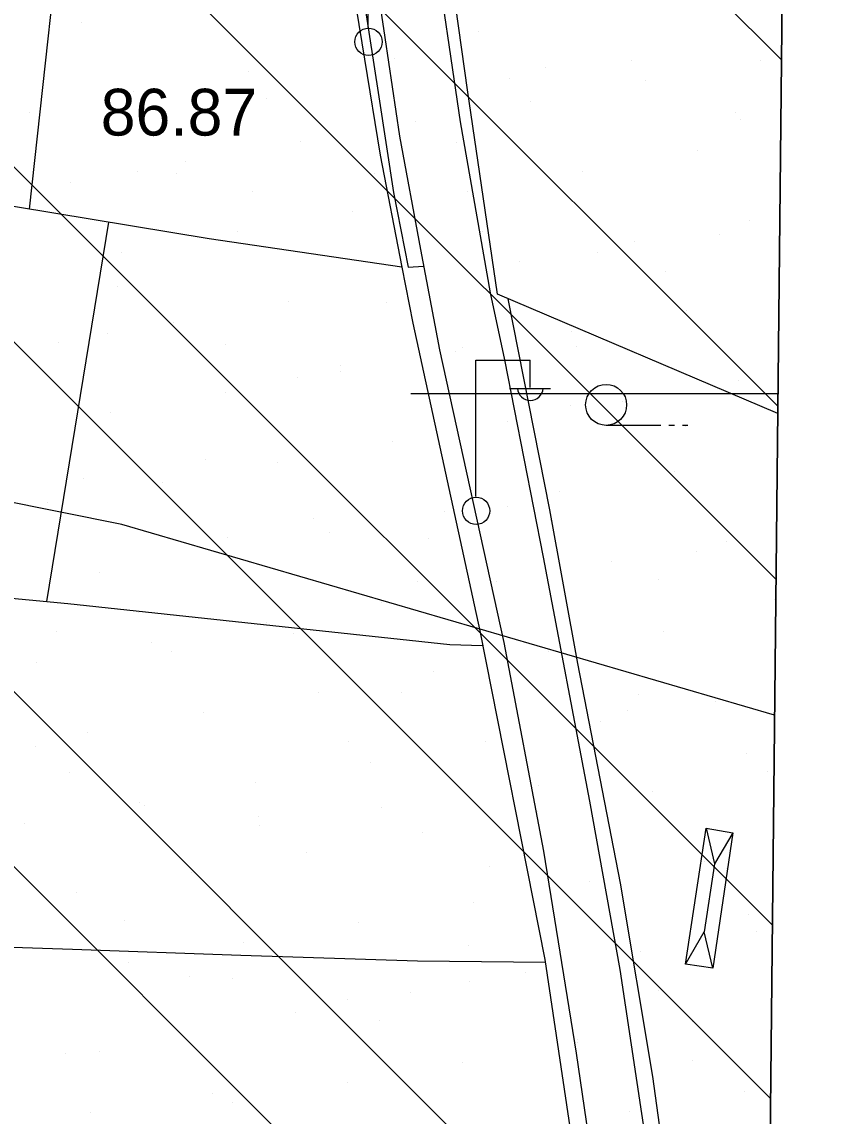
# Model space of a CAD drawing. Extents: x 417995 to 421451, y 4454518 to 4458015.
# Drawn here: x 421182.5 to 421288.3, y 4456164.1 to 4456304.6 of the extents above; entities that cross this region are included whole.
import ezdxf

# ---------------------------------------------------------------- set-up
doc = ezdxf.new("R2010")
doc.units = 0
for name, color, linetype in [('B_Kapi', 7, 'Continuous'), ('B_Sera', 7, 'Continuous'), ('Default', 7, 'Continuous'), ('PAFTALAMA', 7, 'Continuous'), ('PL_AYA_BOLGE_PARKI', 7, 'Continuous'), ('S_Elektrik_Diregi', 7, 'Continuous'), ('S_Tek_Agac', 7, 'Continuous'), ('Sinir_Duvar_tek_tarafa_ait', 7, 'Continuous'), ('Sinir_itirazli_Mulkiyet', 7, 'Continuous'), ('Sinir_Tel_bir_taraf', 7, 'Continuous'), ('SN_TASKIN', 7, 'Continuous'), ('SN_TR_SIVILASMA', 7, 'Continuous'), ('SN_TR_TASKIN', 7, 'Continuous'), ('TR_PARKALANI', 7, 'Continuous'), ('Y_Kot_Noktasi', 7, 'Continuous'), ('Y_Lejant', 7, 'Continuous'), ('Yol_Kaldirim_kenari_bordurtasi', 7, 'Continuous'), ('Yol_Sose', 7, 'Continuous')]:
    doc.layers.add(name, color=color, linetype=linetype)

# ---------------------------------------------------------------- blocks, each defined once
blk = doc.blocks.new('POINT_DISPLAY')
at = {"layer": 'Default'}
blk.add_line((0, 0), (0, 0), dxfattribs=at)

msp = doc.modelspace()

# ---------------------------------------------------------------- linework, layer by layer
at = {"layer": 'B_Kapi'}
msp.add_lwpolyline([(421231.27, 4456273.1), (421232.67, 4456265.92)], dxfattribs=at)
at = {"layer": 'B_Sera'}
for p, q in [((421270.31, 4456201.1), (421271.37, 4456196.51)), ((421273.72, 4456200.52), (421271.37, 4456196.51)), ((421271.37, 4456196.51), (421270.06, 4456187.8)), ((421267.65, 4456183.66), (421270.06, 4456187.8)), ((421271.15, 4456183.15), (421270.06, 4456187.8))]:
    msp.add_line(p, q, dxfattribs=at)
msp.add_lwpolyline([(421270.31, 4456201.1), (421273.72, 4456200.52), (421271.15, 4456183.15), (421267.65, 4456183.66)], close=True, dxfattribs=at)
msp.add_lwpolyline([(421270.31, 4456201.1), (421273.72, 4456200.52), (421271.15, 4456183.15), (421267.65, 4456183.66)], close=True, dxfattribs=at)
at = {"layer": 'PAFTALAMA'}
msp.add_line((421266.41, 4454999.4), (421295.36, 4457775.52), dxfattribs=at)
at = {"layer": 'PL_AYA_BOLGE_PARKI'}
msp.add_line((421271.52, 4455489.32), (421283.96, 4456682.26), dxfattribs=at)
at = {"layer": 'S_Elektrik_Diregi'}
for p, q in [((421226.95, 4456303.87), (421226.95, 4456321.37)), ((421240.75, 4456243.67), (421240.75, 4456261.17)), ((421240.75, 4456261.17), (421247.75, 4456261.17)), ((421247.75, 4456257.67), (421247.75, 4456261.17)), ((421245.09, 4456257.53), (421250.34, 4456257.53))]:
    msp.add_line(p, q, dxfattribs=at)
for centre in [(421226.98, 4456302.04), (421240.79, 4456241.83)]:
    msp.add_circle(centre, 1.75, dxfattribs=at)
msp.add_arc((421247.75, 4456257.68), 1.66, 184.8384, 355.1464, dxfattribs=at)
at = {"layer": 'S_Tek_Agac'}
for p, q in [((421257.48, 4456252.82), (421264.48, 4456252.82)), ((421265.53, 4456252.82), (421266.23, 4456252.82)), ((421267.28, 4456252.82), (421267.98, 4456252.82))]:
    msp.add_line(p, q, dxfattribs=at)
msp.add_circle((421257.48, 4456255.44), 2.63, dxfattribs=at)
at = {"layer": 'Sinir_Duvar_tek_tarafa_ait'}
msp.add_lwpolyline([(421279.5, 4456254.32), (421243.52, 4456269.65), (421239.69, 4456295.88), (421233.98, 4456336.38), (421245.05, 4456395.09), (421256.04, 4456451.41), (421264.42, 4456494.51)], dxfattribs=at)
at = {"layer": 'Sinir_itirazli_Mulkiyet'}
for points in [[(421183.5, 4456280.55), (421188.57, 4456327.06), (421193.19, 4456362.47)], [(421193.61, 4456278.88), (421185.68, 4456230.19)], [(421061.34, 4456243.49), (421108.54, 4456239.12), (421146.38, 4456233.93), (421188.39, 4456229.93), (421237.4, 4456224.69), (421241.62, 4456224.56)], [(421249.69, 4456183.87), (421233.27, 4456184.05), (421210.62, 4456184.74), (421188.98, 4456185.53), (421155.63, 4456186.64), (421142.24, 4456187), (421131.24, 4456186.86), (421120.32, 4456186.91), (421109.49, 4456186.69), (421103.21, 4456186.79), (421093.59, 4456186.7)]]:
    msp.add_lwpolyline(points, dxfattribs=at)
at = {"layer": 'Sinir_Tel_bir_taraf'}
for points in [[(421219.78, 4456356.71), (421220.55, 4456342.44), (421222.49, 4456325.62), (421224.35, 4456312.93), (421226.46, 4456299.8), (421228.5, 4456287.47), (421231.27, 4456273.1)], [(421231.27, 4456273.1), (421206.53, 4456276.75), (421171.54, 4456282.52), (421141.02, 4456287.62), (421113.48, 4456292.17), (421076.4, 4456298.69), (421058.94, 4456301.42), (421042.62, 4456304.08), (421029.03, 4456306.45)], [(421272.11, 4456139.41), (421268.52, 4456139.36), (421267.25, 4456141.93), (421263.49, 4456169.24), (421259.33, 4456194.04), (421253.86, 4456222.25), (421250.27, 4456241.97), (421244.91, 4456269.05)], [(421232.67, 4456265.92), (421241.25, 4456226.44), (421249.63, 4456184.25)], [(421249.63, 4456184.25), (421253.1, 4456160.69), (421256.15, 4456135.73)]]:
    msp.add_lwpolyline(points, dxfattribs=at)
at = {"layer": 'SN_TASKIN'}
msp.add_lwpolyline([(421279.09, 4456215.61), (421195.31, 4456240.09), (421032.23, 4456272.97), (420928.59, 4456320.69), (420834.21, 4456393.35), (420746.64, 4456480.52), (420663.92, 4456586.47), (420574.11, 4456669.5), (420422.96, 4456744.08), (420282.11, 4456812), (420160.8, 4456835.05), (420091.41, 4456837.4), (419960.89, 4456961.81), (419854.4, 4457049.62), (419750.61, 4457217.33), (419705.67, 4457319.89), (419669.27, 4457550.58), (419656.39, 4457729.95), (419636.42, 4457793.06)], dxfattribs=at)
at = {"layer": 'SN_TR_SIVILASMA'}
for p, q in [((421279.97, 4456299.72), (420042.61, 4457537.08)), ((421279.51, 4456255.28), (420030.45, 4457504.34)), ((421279.27, 4456233.06), (420024.37, 4457487.97)), ((421278.81, 4456188.63), (420012.21, 4457455.23)), ((421278.58, 4456166.41), (420006.13, 4457438.86)), ((421278.12, 4456121.97), (419993.97, 4457406.12)), ((421277.88, 4456099.75), (419987.89, 4457389.75))]:
    msp.add_line(p, q, dxfattribs=at)
at = {"layer": 'SN_TR_TASKIN'}
msp.add_line((421232.43, 4456256.9), (421279.52, 4456256.9), dxfattribs=at)
at = {"layer": 'Y_Lejant'}
msp.add_lwpolyline([(419168.18, 4457798.01), (421295.36, 4457775.52), (421266.41, 4454999.4), (419138.44, 4455021.89)], close=True, dxfattribs=at)
at = {"layer": 'Yol_Kaldirim_kenari_bordurtasi'}
msp.add_lwpolyline([(421221.2, 4456358.3), (421221.66, 4456346.45), (421222.33, 4456337.27), (421224.02, 4456323.87), (421225.75, 4456311.61), (421228.32, 4456294.96), (421230.21, 4456282.7), (421232.07, 4456273.1), (421234.05, 4456273.26)], dxfattribs=at)
at = {"layer": 'Yol_Sose'}
for points in [[(421266.67, 4456140.44), (421265.83, 4456141.33), (421265.61, 4456141.91), (421264.25, 4456149.99), (421259.26, 4456182.96), (421255.4, 4456204.55), (421249.45, 4456235.9), (421244.48, 4456261.21), (421242.64, 4456269.8), (421238.79, 4456291.75), (421235.33, 4456315.35), (421232.59, 4456334.58), (421232.53, 4456336.65), (421238.77, 4456368.9), (421247.59, 4456416.23), (421255.57, 4456454.59), (421263.65, 4456494.99)], [(421222.03, 4456357.98), (421223.41, 4456356.21), (421223.71, 4456354.91), (421224.12, 4456344.8), (421225.04, 4456332.99), (421227.26, 4456314.97), (421229.07, 4456302.59), (421230.97, 4456289.93), (421233.64, 4456275.39), (421236.1, 4456262.52), (421244.37, 4456224.92), (421249.42, 4456198.13), (421253.65, 4456172.22), (421256.94, 4456149.71), (421258.54, 4456135.19), (421258.9, 4456125.03), (421258.2, 4456103.09), (421256.41, 4456072.81), (421255.37, 4456050.96), (421252.67, 4456025.65), (421248.93, 4455996.36)]]:
    msp.add_lwpolyline(points, dxfattribs=at)

# ---------------------------------------------------------------- block references
at = {"layer": 'TR_PARKALANI', "xscale": 0.1, "yscale": 0.10000000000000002}
for p in [(421190.13, 4456304.58), (421241.11, 4456303.41), (421226.33, 4456300.81), (421230.35, 4456299.93), (421260.77, 4456299.64), (421277.31, 4456299.64), (421211.56, 4456298.2), (421249.71, 4456298.71), (421245.13, 4456297.32), (421262.54, 4456297.04), (421196.79, 4456295.6), (421213.87, 4456294.75), (421247.77, 4456294.43), (421183.43, 4456292.97), (421274.06, 4456293.03), (421274.67, 4456292.11), (421232.99, 4456291.83), (421218.22, 4456289.22), (421238.22, 4456289.07), (421269.2, 4456288.06), (421203.45, 4456286.62), (421197.34, 4456285.44), (421202.38, 4456285.1), (421227.75, 4456285.16), (421254.43, 4456285.45), (421188.68, 4456284.01), (421212.11, 4456282.84), (421239.65, 4456282.85), (421224.88, 4456280.24), (421275.86, 4456279.08), (421210.11, 4456277.64), (421241.65, 4456277.63), (421272.07, 4456277.34), (421261.09, 4456276.47), (421195.34, 4456275.03), (421246.31, 4456273.87), (421256.43, 4456275.02), (421265.16, 4456272.51), (421231.54, 4456271.26), (421194.73, 4456270.67), (421216.77, 4456268.66), (421229.33, 4456268.55), (421267.75, 4456267.49), (421202, 4456266.05), (421193.49, 4456264.59), (421252.98, 4456264.89), (421187.23, 4456263.45), (421208.64, 4456263.14), (421239.05, 4456262.85), (421253.67, 4456262.87), (421238.2, 4456262.28), (421223.41, 4456260.54), (421223.43, 4456259.68), (421217.84, 4456258.91), (421274.41, 4456258.51), (421208.66, 4456257.07), (421259.64, 4456255.91), (421193.89, 4456254.47), (421252.95, 4456255.33), (421244.86, 4456253.3), (421267.72, 4456252.72), (421230.09, 4456250.7), (421206.03, 4456248.37), (421215.32, 4456248.09), (421190.39, 4456246.05), (421266.3, 4456246.93), (421200.55, 4456245.49), (421251.52, 4456244.32), (421185.78, 4456242.88), (421236.75, 4456241.72), (421244.78, 4456242.36), (421219.93, 4456240.84), (421250.35, 4456240.55), (421221.98, 4456239.11), (421208.94, 4456238.39), (421234.71, 4456238.23), (421272.96, 4456237.95), (421207.21, 4456236.51), (421269.13, 4456236.68), (421258.18, 4456235.34), (421192.44, 4456233.9), (421264.25, 4456233.03), (421233.29, 4456232.71), (421243.41, 4456232.74), (421228.64, 4456230.13), (421279.02, 4456230.42), (421197.45, 4456228.75), (421213.87, 4456227.53), (421186.92, 4456226.35), (421217.33, 4456226.07), (421264.85, 4456226.36), (421199.1, 4456224.92), (421201.69, 4456223.75), (421250.07, 4456223.76), (421184.32, 4456222.32), (421235.3, 4456221.15), (421220.53, 4456218.55), (421231.23, 4456218.54), (421261.65, 4456218.25), (421260.23, 4456216.16), (421271.51, 4456217.38), (421205.76, 4456215.94), (421246.01, 4456215.93), (421256.73, 4456214.78), (421190.98, 4456213.34), (421224.4, 4456212.2), (421241.96, 4456212.17), (421184.31, 4456211.58), (421275.55, 4456210.72), (421227.19, 4456209.57), (421188.56, 4456208.24), (421278.17, 4456208.4), (421212.42, 4456206.96), (421248.74, 4456206.52), (421263.39, 4456205.8), (421197.65, 4456204.36), (421198.22, 4456204.05), (421228.63, 4456203.77), (421212.9, 4456202.56), (421248.62, 4456203.19), (421182.87, 4456201.76), (421212.99, 4456201.45), (421233.85, 4456200.59), (421219.08, 4456197.98), (421270.05, 4456196.82), (421204.31, 4456195.38), (421242.53, 4456196.24), (421272.95, 4456195.95), (421255.28, 4456194.21), (421257.31, 4456193.63), (421189.53, 4456192.78), (421240.51, 4456191.61), (421275.69, 4456189.97), (421195.61, 4456189.28), (421225.74, 4456189.01), (421276.72, 4456187.84), (421210.97, 4456186.4), (421239.85, 4456186), (421261.94, 4456185.23), (421196.19, 4456183.8), (421247.17, 4456182.63), (421204.01, 4456182.04), (421209.52, 4456181.75), (421239.93, 4456181.47), (421232.4, 4456180.03), (421264.2, 4456180.32), (421224.29, 4456179.15), (421217.63, 4456177.42), (421228.36, 4456176.36), (421268.6, 4456176.25), (421202.85, 4456174.82), (421253.83, 4456173.94), (421253.83, 4456173.65), (421188.08, 4456172.21), (421192.52, 4456172.4), (421268.6, 4456171.33), (421239.06, 4456171.05), (421224.29, 4456168.44), (421206.91, 4456166.98), (421275.26, 4456167.28), (421209.52, 4456165.84), (421191.27, 4456164.66), (421260.49, 4456164.67)]:
    msp.add_blockref('POINT_DISPLAY', p, dxfattribs=at)

# ---------------------------------------------------------------- texts
at = {"layer": 'Y_Kot_Noktasi'}
msp.add_text('86.87', height=6, dxfattribs=at).set_placement((421192.62, 4456290.01))

doc.saveas('drawing.dxf')
